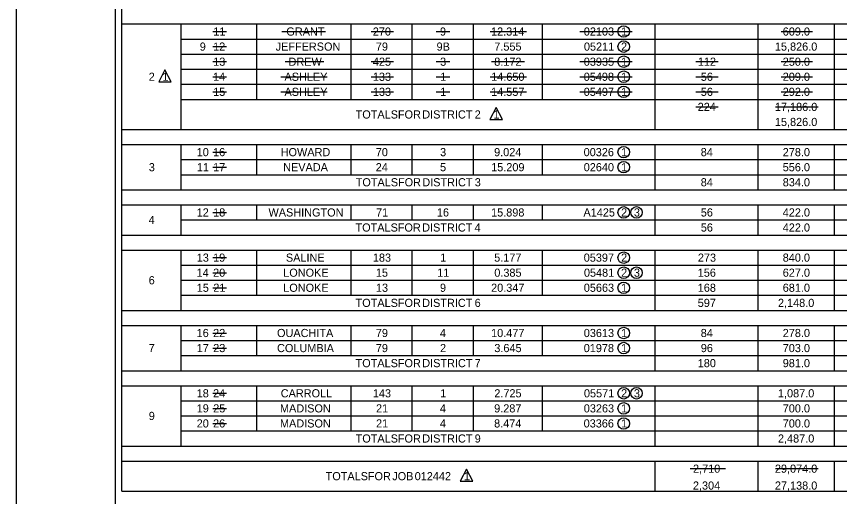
# Model space of a CAD drawing. Extents: x 18 to 14744716, y -5 to 1829144.
# Drawn here: x 17.78 to 30.4, y 3.12 to 10.48 of the extents above; entities that cross this region are included whole.
import ezdxf

# ---------------------------------------------------------------- set-up
doc = ezdxf.new("R2010")
doc.units = 0
for name, color, linetype in [('B_Dimensions', 7, 'Continuous'), ('B_Text', 7, 'Continuous'), ('R_Border', 7, 'Continuous'), ('R_No Plot', 7, 'Continuous')]:
    doc.layers.add(name, color=color, linetype=linetype)

msp = doc.modelspace()

# ---------------------------------------------------------------- linework, layer by layer
at = {"layer": 'B_Dimensions'}
for p, q in [((20.786, 10.252), (20.996, 10.252)), ((21.843, 10.252), (22.513, 10.252)), ((23.215, 10.252), (23.559, 10.252)), ((24.213, 10.252), (24.423, 10.252)), ((25.04, 10.252), (25.596, 10.252)), ((26.412, 10.252), (27.216, 10.252)), ((29.503, 10.252), (29.979, 10.252)), ((20.786, 10.021), (20.996, 10.021)), ((20.786, 9.79), (20.996, 9.79)), ((21.896, 9.79), (22.487, 9.79)), ((23.215, 9.79), (23.559, 9.79)), ((24.213, 9.79), (24.423, 9.79)), ((25.062, 9.79), (25.565, 9.79)), ((26.412, 9.79), (27.216, 9.79)), ((28.194, 9.79), (28.537, 9.79)), ((29.503, 9.79), (29.979, 9.79)), ((20.054, 9.666), (19.958, 9.482)), ((20.151, 9.482), (20.054, 9.666)), ((19.958, 9.482), (20.151, 9.482)), ((20.786, 9.559), (20.996, 9.559)), ((21.828, 9.559), (22.54, 9.559)), ((23.215, 9.559), (23.559, 9.559)), ((24.213, 9.559), (24.423, 9.559)), ((25.04, 9.559), (25.596, 9.559)), ((26.412, 9.559), (27.216, 9.559)), ((28.194, 9.559), (28.537, 9.559)), ((29.503, 9.559), (29.979, 9.559)), ((20.786, 9.327), (20.996, 9.327)), ((21.828, 9.327), (22.54, 9.327)), ((23.215, 9.327), (23.559, 9.327)), ((24.213, 9.327), (24.423, 9.327)), ((25.04, 9.327), (25.596, 9.327)), ((26.412, 9.327), (27.216, 9.327)), ((28.194, 9.327), (28.537, 9.327)), ((29.503, 9.327), (29.979, 9.327)), ((25.13, 9.088), (25.034, 8.904)), ((25.227, 8.904), (25.13, 9.088)), ((28.194, 9.096), (28.537, 9.096)), ((29.412, 9.096), (30.068, 9.096)), ((25.034, 8.904), (25.227, 8.904)), ((20.786, 8.403), (20.996, 8.403)), ((20.786, 8.171), (20.996, 8.171)), ((20.786, 7.478), (20.996, 7.478)), ((20.786, 6.784), (20.996, 6.784)), ((20.786, 6.553), (20.996, 6.553)), ((20.786, 6.322), (20.996, 6.322)), ((20.786, 5.628), (20.996, 5.628)), ((20.786, 5.397), (20.996, 5.397)), ((20.786, 4.704), (20.996, 4.704)), ((20.786, 4.472), (20.996, 4.472)), ((20.786, 4.241), (20.996, 4.241)), ((24.678, 3.54), (24.582, 3.356)), ((24.775, 3.356), (24.678, 3.54)), ((28.106, 3.548), (28.648, 3.548)), ((29.412, 3.548), (30.068, 3.548)), ((24.582, 3.356), (24.775, 3.356))]:
    msp.add_line(p, q, dxfattribs=at)
for centre in [(27.087, 10.252), (27.087, 10.021), (27.087, 9.79), (27.087, 9.559), (27.087, 9.327), (27.087, 8.403), (27.087, 8.171), (27.087, 7.478), (27.283, 7.478), (27.087, 6.784), (27.087, 6.553), (27.283, 6.553), (27.087, 6.322), (27.087, 5.628), (27.087, 5.397), (27.087, 4.704), (27.283, 4.704), (27.087, 4.472), (27.087, 4.241)]:
    msp.add_circle(centre, 0.0881, dxfattribs=at)
at = {"layer": 'B_Text'}
for p, q in [((19.392, 3.201), (19.392, 14.979)), ((19.392, 10.368), (51.101, 10.368)), ((20.304, 8.749), (20.304, 10.368)), ((21.46, 9.212), (21.46, 10.368)), ((22.908, 9.212), (22.908, 10.368)), ((23.845, 9.212), (23.845, 10.368)), ((24.782, 9.212), (24.782, 10.368)), ((25.841, 9.212), (25.841, 10.368)), ((27.569, 8.749), (27.569, 10.368)), ((29.15, 8.749), (29.15, 10.368)), ((30.318, 8.749), (30.318, 10.368)), ((20.304, 10.137), (51.101, 10.137)), ((20.304, 9.905), (51.101, 9.905)), ((20.304, 9.674), (51.101, 9.674)), ((20.304, 9.443), (51.101, 9.443)), ((20.304, 9.212), (51.101, 9.212)), ((19.392, 8.749), (51.101, 8.749)), ((19.392, 8.518), (46.392, 8.518)), ((19.392, 8.518), (44.823, 8.518)), ((20.304, 7.825), (20.304, 8.518)), ((21.46, 8.056), (21.46, 8.518)), ((22.908, 8.056), (22.908, 8.518)), ((23.845, 8.056), (23.845, 8.518)), ((24.782, 8.056), (24.782, 8.518)), ((25.841, 8.056), (25.841, 8.518)), ((27.569, 7.825), (27.569, 8.518)), ((29.15, 7.825), (29.15, 8.518)), ((30.318, 7.825), (30.318, 8.518)), ((20.304, 8.287), (51.101, 8.287)), ((20.304, 8.056), (51.101, 8.056)), ((19.392, 7.825), (51.101, 7.825)), ((19.392, 7.593), (46.392, 7.593)), ((19.392, 7.593), (44.823, 7.593)), ((20.304, 7.131), (20.304, 7.593)), ((21.46, 7.362), (21.46, 7.593)), ((22.908, 7.362), (22.908, 7.593)), ((23.845, 7.362), (23.845, 7.593)), ((24.782, 7.362), (24.782, 7.593)), ((25.841, 7.362), (25.841, 7.593)), ((27.569, 7.131), (27.569, 7.593)), ((29.15, 7.131), (29.15, 7.593)), ((30.318, 7.131), (30.318, 7.593)), ((20.304, 7.362), (51.101, 7.362)), ((19.392, 7.131), (51.101, 7.131)), ((19.392, 6.9), (46.392, 6.9)), ((19.392, 6.9), (44.823, 6.9)), ((20.304, 5.975), (20.304, 6.9)), ((21.46, 6.206), (21.46, 6.9)), ((22.908, 6.206), (22.908, 6.9)), ((23.845, 6.206), (23.845, 6.9)), ((24.782, 6.206), (24.782, 6.9)), ((25.841, 6.206), (25.841, 6.9)), ((27.569, 5.975), (27.569, 6.9)), ((29.15, 5.975), (29.15, 6.9)), ((30.318, 5.975), (30.318, 6.9)), ((20.304, 6.669), (51.101, 6.669)), ((20.304, 6.438), (51.101, 6.438)), ((20.304, 6.206), (51.101, 6.206)), ((19.392, 5.975), (51.101, 5.975)), ((19.392, 5.744), (46.392, 5.744)), ((19.392, 5.744), (44.823, 5.744)), ((20.304, 5.05), (20.304, 5.744)), ((21.46, 5.282), (21.46, 5.744)), ((22.908, 5.282), (22.908, 5.744)), ((23.845, 5.282), (23.845, 5.744)), ((24.782, 5.282), (24.782, 5.744)), ((25.841, 5.282), (25.841, 5.744)), ((27.569, 5.05), (27.569, 5.744)), ((29.15, 5.05), (29.15, 5.744)), ((30.318, 5.05), (30.318, 5.744)), ((20.304, 5.513), (51.101, 5.513)), ((20.304, 5.282), (51.101, 5.282)), ((19.392, 5.05), (51.101, 5.05)), ((19.392, 4.819), (46.392, 4.819)), ((19.392, 4.819), (44.823, 4.819)), ((20.304, 3.894), (20.304, 4.819)), ((21.46, 4.126), (21.46, 4.819)), ((22.908, 4.126), (22.908, 4.819)), ((23.845, 4.126), (23.845, 4.819)), ((24.782, 4.126), (24.782, 4.819)), ((25.841, 4.126), (25.841, 4.819)), ((27.569, 3.894), (27.569, 4.819)), ((29.15, 3.894), (29.15, 4.819)), ((30.318, 3.894), (30.318, 4.819)), ((20.304, 4.588), (51.101, 4.588)), ((20.304, 4.357), (51.101, 4.357)), ((20.304, 4.126), (51.101, 4.126)), ((19.392, 3.894), (51.101, 3.894)), ((19.392, 3.663), (46.392, 3.663)), ((19.392, 3.663), (44.823, 3.663)), ((27.569, 3.201), (27.569, 3.663)), ((29.15, 3.201), (29.15, 3.663)), ((30.318, 3.201), (30.318, 3.663)), ((19.392, 3.201), (51.101, 3.201))]:
    msp.add_line(p, q, dxfattribs=at)
at = {"layer": 'R_Border'}
msp.add_line((19.293, -4.796), (19.293, 16.051), dxfattribs=at)
at = {"layer": 'R_No Plot'}
msp.add_lwpolyline([(17.777, 16.628), (51.777, 16.628), (51.777, -5.372), (17.777, -5.372)], close=True, dxfattribs=at)

# ---------------------------------------------------------------- texts
at = {"layer": 'B_Text'}
for s, height, p in [('11', 0.1248, (20.795, 10.19)), ('GRANT', 0.1248, (21.915, 10.19)), ('270', 0.1248, (23.24, 10.19)), ('9', 0.125, (24.27, 10.19)), ('12.314', 0.1248, (25.053, 10.19)), ('02103', 0.1248, (26.475, 10.19)), ('1', 0.125, (27.047, 10.19)), ('609.0', 0.1248, (29.525, 10.19)), ('9', 0.125, (20.587, 9.959)), ('12', 0.1248, (20.792, 9.959)), ('JEFFERSON', 0.1248, (21.75, 9.959)), ('79', 0.1248, (23.287, 9.959)), ('9B', 0.1248, (24.218, 9.959)), ('7.555', 0.1248, (25.103, 9.959)), ('05211', 0.1248, (26.477, 9.959)), ('2', 0.125, (27.047, 9.959)), ('15,826.0', 0.1248, (29.405, 9.959)), ('13', 0.1248, (20.793, 9.727)), ('DREW', 0.1248, (21.948, 9.727)), ('425', 0.1248, (23.241, 9.727)), ('3', 0.125, (24.272, 9.727)), ('8.172', 0.1248, (25.102, 9.727)), ('03935', 0.1248, (26.475, 9.727)), ('1', 0.125, (27.047, 9.727)), ('112', 0.1248, (28.223, 9.727)), ('250.0', 0.1248, (29.525, 9.727)), ('2', 0.125, (19.805, 9.496)), ('1', 0.125, (20.014, 9.496)), ('14', 0.1248, (20.791, 9.496)), ('ASHLEY', 0.1248, (21.886, 9.496)), ('133', 0.1248, (23.241, 9.496)), ('1', 0.125, (24.274, 9.496)), ('14.650', 0.1248, (25.055, 9.496)), ('05498', 0.1248, (26.474, 9.496)), ('1', 0.125, (27.047, 9.496)), ('56', 0.1248, (28.269, 9.496)), ('209.0', 0.1248, (29.525, 9.496)), ('15', 0.1248, (20.793, 9.265)), ('ASHLEY', 0.1248, (21.886, 9.265)), ('133', 0.1248, (23.241, 9.265)), ('1', 0.125, (24.274, 9.265)), ('14.557', 0.1248, (25.054, 9.265)), ('05497', 0.1248, (26.474, 9.265)), ('1', 0.125, (27.047, 9.265)), ('56', 0.1248, (28.269, 9.265)), ('292.0', 0.1248, (29.525, 9.265)), ('224', 0.1248, (28.221, 9.034)), ('17,186.0', 0.1248, (29.405, 9.034)), ('TOTALS', 0.1248, (22.977, 8.918)), (' FOR', 0.1248, (23.579, 8.918)), (' DISTRICT', 0.1248, (23.952, 8.918)), (' 2', 0.1248, (24.756, 8.918)), ('1', 0.125, (25.09, 8.918)), ('15,826.0', 0.1248, (29.405, 8.803)), ('10', 0.1248, (20.54, 8.34)), ('16', 0.1248, (20.791, 8.34)), ('HOWARD', 0.1248, (21.828, 8.34)), ('70', 0.1248, (23.286, 8.34)), ('3', 0.125, (24.272, 8.34)), ('9.024', 0.1248, (25.1, 8.34)), ('00326', 0.1248, (26.473, 8.34)), ('1', 0.125, (27.047, 8.34)), ('84', 0.1248, (28.268, 8.34)), ('278.0', 0.1248, (29.525, 8.34)), ('3', 0.125, (19.806, 8.109)), ('11', 0.1248, (20.543, 8.109)), ('17', 0.1248, (20.792, 8.109)), ('NEVADA', 0.1248, (21.866, 8.109)), ('24', 0.1248, (23.285, 8.109)), ('5', 0.125, (24.271, 8.109)), ('15.209', 0.1248, (25.055, 8.109)), ('02640', 0.1248, (26.474, 8.109)), ('1', 0.125, (27.047, 8.109)), ('556.0', 0.1248, (29.525, 8.109)), ('TOTALS', 0.1248, (22.978, 7.878)), (' FOR', 0.1248, (23.58, 7.878)), (' DISTRICT', 0.1248, (23.953, 7.878)), (' 3', 0.1248, (24.757, 7.878)), ('84', 0.1248, (28.268, 7.878)), ('834.0', 0.1248, (29.525, 7.878)), ('12', 0.1248, (20.54, 7.415)), ('18', 0.1248, (20.792, 7.415)), ('WASHINGTON', 0.1248, (21.641, 7.415)), ('71', 0.1248, (23.29, 7.415)), ('16', 0.1248, (24.223, 7.415)), ('15.898', 0.1248, (25.054, 7.415)), ('A1425', 0.1248, (26.47, 7.415)), ('2', 0.125, (27.047, 7.415)), ('3', 0.125, (27.243, 7.415)), ('56', 0.1248, (28.269, 7.415)), ('422.0', 0.1248, (29.525, 7.415)), ('4', 0.125, (19.803, 7.3)), ('TOTALS', 0.1248, (22.975, 7.184)), (' FOR', 0.1248, (23.577, 7.184)), (' DISTRICT', 0.1248, (23.951, 7.184)), (' 4', 0.1248, (24.754, 7.184)), ('56', 0.1248, (28.269, 7.184)), ('422.0', 0.1248, (29.525, 7.184)), ('13', 0.1248, (20.541, 6.722)), ('19', 0.1248, (20.792, 6.722)), ('SALINE', 0.1248, (21.908, 6.722)), ('183', 0.1248, (23.241, 6.722)), ('1', 0.125, (24.274, 6.722)), ('5.177', 0.1248, (25.101, 6.722)), ('05397', 0.1248, (26.474, 6.722)), ('2', 0.125, (27.047, 6.722)), ('273', 0.1248, (28.224, 6.722)), ('840.0', 0.1248, (29.525, 6.722)), ('14', 0.1248, (20.539, 6.491)), ('20', 0.1248, (20.792, 6.491)), ('LONOKE', 0.1248, (21.867, 6.491)), ('15', 0.1248, (23.287, 6.491)), ('11', 0.1248, (24.227, 6.491)), ('0.385', 0.1248, (25.103, 6.491)), ('05481', 0.1248, (26.477, 6.491)), ('2', 0.125, (27.047, 6.491)), ('3', 0.125, (27.243, 6.491)), ('156', 0.1248, (28.222, 6.491)), ('627.0', 0.1248, (29.525, 6.491)), ('6', 0.125, (19.804, 6.375)), ('15', 0.1248, (20.541, 6.26)), ('21', 0.1248, (20.795, 6.26)), ('LONOKE', 0.1248, (21.867, 6.26)), ('13', 0.1248, (23.288, 6.26)), ('9', 0.125, (24.27, 6.26)), ('20.347', 0.1248, (25.054, 6.26)), ('05663', 0.1248, (26.475, 6.26)), ('1', 0.125, (27.047, 6.26)), ('168', 0.1248, (28.222, 6.26)), ('681.0', 0.1248, (29.525, 6.26)), ('TOTALS', 0.1248, (22.976, 6.028)), (' FOR', 0.1248, (23.578, 6.028)), (' DISTRICT', 0.1248, (23.951, 6.028)), (' 6', 0.1248, (24.755, 6.028)), ('597', 0.1248, (28.222, 6.028)), ('2,148.0', 0.1248, (29.452, 6.028)), ('16', 0.1248, (20.539, 5.566)), ('22', 0.1248, (20.792, 5.566)), ('OUACHITA', 0.1248, (21.772, 5.566)), ('79', 0.1248, (23.287, 5.566)), ('4', 0.125, (24.269, 5.566)), ('10.477', 0.1248, (25.054, 5.566)), ('03613', 0.1248, (26.475, 5.566)), ('1', 0.125, (27.047, 5.566)), ('84', 0.1248, (28.268, 5.566)), ('278.0', 0.1248, (29.525, 5.566)), ('7', 0.125, (19.804, 5.335)), ('17', 0.1248, (20.54, 5.335)), ('23', 0.1248, (20.793, 5.335)), ('COLUMBIA', 0.1248, (21.772, 5.335)), ('79', 0.1248, (23.287, 5.335)), ('2', 0.125, (24.271, 5.335)), ('3.645', 0.1248, (25.103, 5.335)), ('01978', 0.1248, (26.474, 5.335)), ('1', 0.125, (27.047, 5.335)), ('96', 0.1248, (28.269, 5.335)), ('703.0', 0.1248, (29.525, 5.335)), ('TOTALS', 0.1248, (22.976, 5.104)), (' FOR', 0.1248, (23.578, 5.104)), (' DISTRICT', 0.1248, (23.952, 5.104)), (' 7', 0.1248, (24.755, 5.104)), ('180', 0.1248, (28.222, 5.104)), ('981.0', 0.1248, (29.525, 5.104)), ('18', 0.1248, (20.54, 4.641)), ('24', 0.1248, (20.791, 4.641)), ('CARROLL', 0.1248, (21.829, 4.641)), ('143', 0.1248, (23.241, 4.641)), ('1', 0.125, (24.274, 4.641)), ('2.725', 0.1248, (25.103, 4.641)), ('05571', 0.1248, (26.477, 4.641)), ('2', 0.125, (27.047, 4.641)), ('3', 0.125, (27.243, 4.641)), ('1,087.0', 0.1248, (29.452, 4.641)), ('9', 0.125, (19.805, 4.294)), ('19', 0.1248, (20.54, 4.41)), ('25', 0.1248, (20.793, 4.41)), ('MADISON', 0.1248, (21.817, 4.41)), ('21', 0.1248, (23.29, 4.41)), ('4', 0.125, (24.269, 4.41)), ('9.287', 0.1248, (25.101, 4.41)), ('03263', 0.1248, (26.475, 4.41)), ('1', 0.125, (27.047, 4.41)), ('700.0', 0.1248, (29.525, 4.41)), ('20', 0.1248, (20.54, 4.179)), ('26', 0.1248, (20.791, 4.179)), ('MADISON', 0.1248, (21.817, 4.179)), ('21', 0.1248, (23.29, 4.179)), ('4', 0.125, (24.269, 4.179)), ('8.474', 0.1248, (25.1, 4.179)), ('03366', 0.1248, (26.473, 4.179)), ('1', 0.125, (27.047, 4.179)), ('700.0', 0.1248, (29.525, 4.179)), ('TOTALS', 0.1248, (22.977, 3.948)), (' FOR', 0.1248, (23.578, 3.948)), (' DISTRICT', 0.1248, (23.952, 3.948)), (' 9', 0.1248, (24.756, 3.948)), ('2,487.0', 0.1248, (29.452, 3.948)), ('2,710', 0.1248, (28.15, 3.485)), ('29,074.0', 0.1248, (29.405, 3.485)), ('TOTALS', 0.1248, (22.517, 3.37)), (' FOR', 0.1248, (23.118, 3.37)), (' JOB', 0.1248, (23.492, 3.37)), (' 012442', 0.1248, (23.836, 3.37)), ('1', 0.125, (24.638, 3.37)), ('2,304', 0.1248, (28.148, 3.226)), ('27,138.0', 0.1248, (29.405, 3.226))]:
    msp.add_text(s, height=height, dxfattribs=at).set_placement(p)

doc.saveas('drawing.dxf')
